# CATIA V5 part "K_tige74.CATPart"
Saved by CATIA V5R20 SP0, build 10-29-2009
Part number: tige 74
Publications: "longueur verin commande", "demi largeur tige", "demi largeur balancier", "epaisseur pieces", "Plan.-55", "liaison 21/74 sur 74", "Droite.1", "liaison 21/74 sur 21"
Bounding box of the stored display mesh (mm): x -72.5 to 0, y -497.714 to 132.496, z 482.504 to 681.391
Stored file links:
  G:\Khaled_CFAO_2011\SIL\SIL_GR2\mdardier\Khaled\CAD_ThinkMOTION\K_tige74.CATPart
  G:\Khaled_CFAO_2011\SIL\SIL_GR2\mdardier\Khaled\CAD_ThinkMOTION\K_ass_tandem.CATProduct
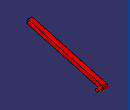
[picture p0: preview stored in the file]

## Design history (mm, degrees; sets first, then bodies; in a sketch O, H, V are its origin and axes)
External parameters (linked from other documents)
  `External.longueur verin commande` = 620 mm
  `External.demi largeur tige` = 17.5 mm
  `External.demi largeur balancier` = 50 mm
  `External.epaisseur pieces` = 30 mm
Set1
  Plane1 "Plan.-55": linked copy from another document
  Point1 "liaison 21/74 sur 74": linked copy from another document
  Line1: linked copy from another document
  Point2 "liaison 21/74 sur 21": linked copy from another document
Body1 (main body)
  Sketch1 on Plane1, origin (-55, 0, 0), H (0, 1, 0), V (0, 0, 1)
    construction line L1 (-493.145, 664.4982) -> (115, 500)
    point P3 (-497.7144, 647.6053)
    construction line L2 (-493.145, 664.4982) -> (115, 500)
    point P4 (115, 500)
    line L3 (-488.5756, 681.3912) -> (119.5694, 516.8929)
    line L4 (110.4306, 483.1071) -> (-497.7144, 647.6053)
    arc A1 centre (115, 500) radius 17.5 from (119.5694, 516.8929) to (110.4306, 483.1071) cw
    reference projected point E1 (115, 500) from Point1
    reference projected line E2 (-493.145, 664.4982) -> (115, 500) from Line1
    line L5 (-488.5756, 681.3912) -> (-497.7144, 647.6053)
    reference projected line E3 (-493.145, 664.4982) -> (115, 500) from Line1
    distance L2 L3 = 17.5 {= `External.demi largeur tige`}
    length L3 = 630 {= `External.longueur verin commande` +0.01}
    tangency: A1 L3, A1 L4
    coincidence: P4 E1
    parallelism: L2 E2
    perpendicularity: L5 L1, L5 L3, L5 E3, L5 L4
  Pad1: profile Sketch1, direction (1, 0, 0), length 17.5 {= `External.demi largeur tige`}, mirrored extent
  Sketch2 on end face of Pad1, origin (-37.5, 0, 0), H (0, 1, 0), V (0, 0, 1)
    circle A1 centre (115, 500) radius 12.5
    point P1 (115, 500)
    reference projected point E1 (115, 500) from Point1
    radius A1 = 12.5 {= `External.demi largeur balancier` /4}
    coincidence: P1 E1
  Pad2: profile Sketch2, direction (1, 0, 0), length 37.5 {= `External.demi largeur balancier` /2-`External.demi largeur tige` +`External.epaisseur pieces`}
